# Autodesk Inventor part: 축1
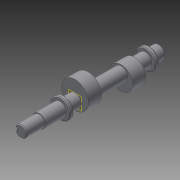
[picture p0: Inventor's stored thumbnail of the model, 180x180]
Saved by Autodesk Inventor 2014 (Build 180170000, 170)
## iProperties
Created: 2014-12
Part Number: 축1
Material: 일반
Document SubType Name: Modeling
Designer: Owner
Density: 1 g/cm^3
Appearance: 기본값
Author: Owner
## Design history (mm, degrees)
sketch "스케치1"
  geometry: L1 (-90, 0)-(90, 0); L2 (-90, 0)-(-90, 7.5); L3 (-90, 7.5)-(-66, 7.5); L4 (-66, 7.5)-(-66, 8.5); L5 (-66, 8.5)-(-39, 8.5); L6 (-39, 8.5)-(-39, 13); L7 (-39, 13)-(-34, 13); L8 (-34, 13)-(-34, 8.5); L9 (-34, 8.5)-(-19.5, 8.5); L10 (-19.5, 8.5)-(72, 8.5); L11 (72, 8.5)-(72, 13); L12 (72, 13)-(77, 13); L13 (77, 13)-(77, 8.5); L14 (77, 8.5)-(90, 8.5); L15 (90, 8.5)-(90, 0); 2 further points
  constraints: 30 end point, 9 parallel, 4 perpendicular, 1 coincident, 1 collinear, 1 horizontal, 1 midpoint
  dimensions: "d0" = 180 distance of L1.end L1.start; "d1" = 24 distance of L2.end L3.end; "d2" = 27 distance of L4.end L5.end; "d3" = 5 distance of L6.end L7.end; "d4" = 14.5 distance of L8.end L9.end; "d5" = 91.5 distance of L9.end L10.end; "d6" = 5 distance of L11.end L12.end; "d7" = 15 diameter of L3 L1; "d8" = 17 diameter of L5 L1; "d9" = 26 diameter of L7 L1; "d10" = 17 diameter of L10 L1; "d12" = 17 diameter of L14 L1; "d13" = 26 diameter of L12 L1
revolve "회전1" sketch "스케치1" stored, may be unused: angle "d14" = 90 deg
node "작업 평면1"
sketch "스케치2"
  geometry: C1 r 8.5 at (0, 0) reference; C2 r 17.5 at (0, 6); 1 further point
  constraints: 1 centre point, 1 vertical alignment
  dimensions: "d16" = 35 diameter of C2; "d17" = 6 distance of C2.centre point (0, 0)
extrude "돌출1" join sketch "스케치2" distance "d18" = 17; taper "d19" = 0 deg
node "작업 평면2"
sketch "스케치3"
  geometry: C1 r 15 at (0, 5); 1 further point
  constraints: 1 centre point, 1 vertical alignment
  dimensions: "d21" = 30 diameter of C1; "d23" = 5 distance of point (0, 0) C1.centre
extrude "돌출2" join sketch "스케치3" distance "d24" = 17; taper "d25" = 0 deg
node "작업 평면3"
sketch "스케치4"
  geometry: 1 further point
sketch "스케치5"
  geometry: L1 (12, 7.5)-(12, -7.5) reference; L2 (-5.5, 0)-(12, 0); L3 (-5.5, -2.5)-(12, -2.5); L4 (12, 2.5)-(-5.5, 2.5); A1 r 2.5 centre (-5.5, 0) between (-5.5, 2.5) and (-5.5, -2.5); 2 further points
  constraints: 8 end point, 2 midpoint, 2 point on circle, 2 point on line, 2 tangent, 1 centre point, 1 horizontal alignment, 1 parallel
  dimensions: "d31" = 5 distance between parallel lines of L4 L3; "d32" = 20 dimension on A1 L1; "d33" = 2.5 distance of L3.end L2.end
extrude "돌출3" cut sketch "스케치5" distance "d34" = 3; taper "d35" = 0 deg
chamfer "모따기1" distance "d36" = 1; stored, may be unused: second distance "d37" = 2, angle "d38" = 45 deg
chamfer "모따기2" distance "d39" = 1; stored, may be unused: second distance "d40" = 2, angle "d41" = 45 deg
chamfer "모따기3" distance "d42" = 1; stored, may be unused: second distance "d43" = 2, angle "d44" = 45 deg
chamfer "모따기4" distance "d45" = 1; stored, may be unused: second distance "d46" = 2, angle "d47" = 45 deg
chamfer "모따기5" distance "d48" = 1; stored, may be unused: second distance "d49" = 2, angle "d50" = 45 deg
chamfer "모따기6" distance "d51" = 1; stored, may be unused: second distance "d52" = 2, angle "d53" = 45 deg
node "솔리드1"
node "투영된 루프1"
other parameters: "d15" = -70.5, "d20" = -32.5
